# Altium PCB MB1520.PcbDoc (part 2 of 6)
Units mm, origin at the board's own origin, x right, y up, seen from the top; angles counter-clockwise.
Board outline 159 x 88 mm, 6 copper layers (Top Layer, Signal Layer 1, Signal Layer 2, Signal Layer 3, Signal Layer 4, Bottom Layer), stack 1.572 mm thick; 473 components, 377 nets, 1832 pads, 1378 vias.
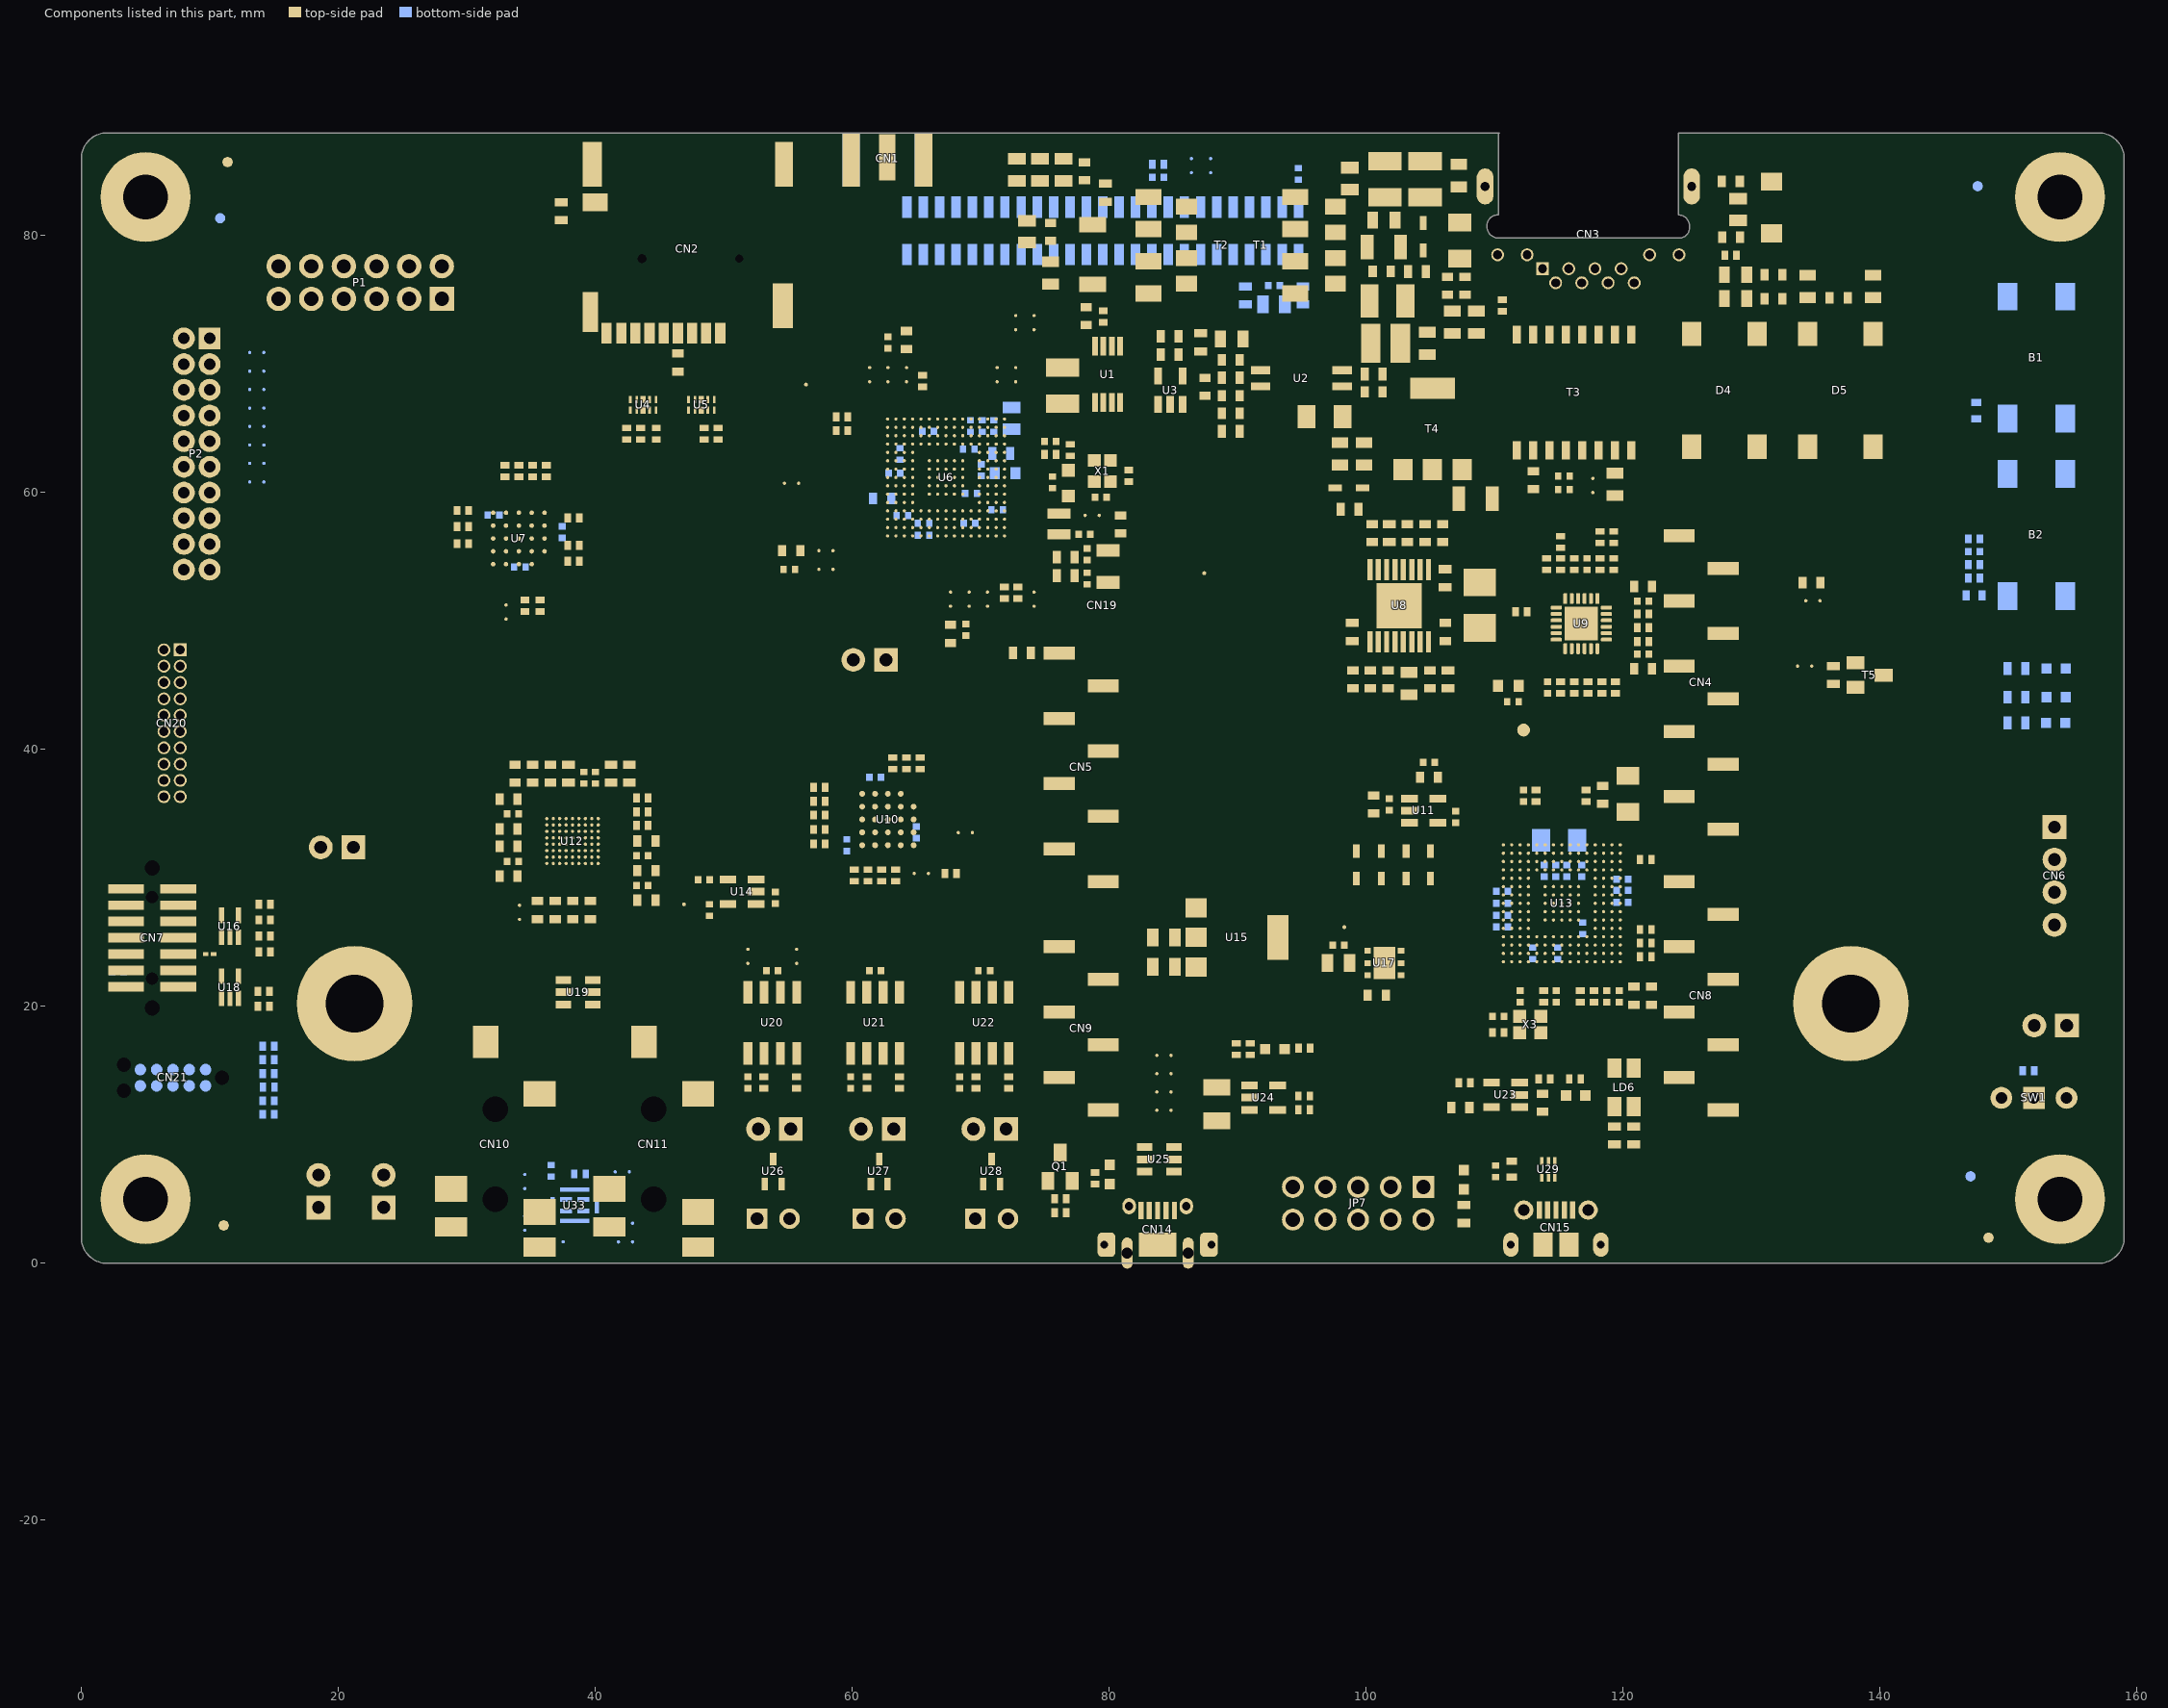
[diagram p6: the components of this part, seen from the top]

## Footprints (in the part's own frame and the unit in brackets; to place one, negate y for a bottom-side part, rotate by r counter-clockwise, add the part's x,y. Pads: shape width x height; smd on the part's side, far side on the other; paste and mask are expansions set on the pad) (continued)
CON_SAMTEC_SQT-110-01-F-D-RA__STMOD+ [mm] "SQT-110-01-F-D-RA (connecteur SAMTEC pour interface STMod+ femelle coté Host) Pinning adapté non conforme SAMTEC."
  rect 1.7x1.7 hole 0.9 mask+0.05: 1(9,1)
  round 1.7 hole 0.9 mask+0.05: 2(7,1) 3(5,1) 4(3,1) 5(1,1) 6(-1,1) 7(-3,1) 8(-5,1) 9(-7,1) 10(-9,1) 11(9,-1) 12(7,-1) 13(5,-1) 14(3,-1) 15(1,-1) 16(-1,-1) 17(-3,-1) 18(-5,-1) 19(-7,-1) 20(-9,-1)
  silkscreen extent -10.15,-8.62 10.15,0.07, body extent -10.15,-8.65 10.15,1.22, height 4
CON_SAMTEC_SSW-106-02-F-D-RA__PMOD [mm] "SSW-106-02-F-D-RA (connecteur SAMTEC pour interface PMOD femelle coté Host) Pinning adapté non conforme SAMTEC."
  rect 1.9x1.9 hole 1.1 mask+0.05: 1(6.35,1.27)
  round 1.9 hole 1.1 mask+0.05: 2(3.81,1.27) 3(1.27,1.27) 4(-1.27,1.27) 5(-3.81,1.27) 6(-6.35,1.27) 7(6.35,-1.27) 8(3.81,-1.27) 9(1.27,-1.27) 10(-1.27,-1.27) 11(-3.81,-1.27) 12(-6.35,-1.27)
  silkscreen extent -7.88,-11.3 7.88,0.23, body extent -7.87,-11.31 7.87,1.47, height 5.21
CON_SAMTEC_SSW-106-22-X-S-VS [mil]
  rect 40x95 smd mask+1.97: 1(250,67.5) 2(150,-67.5) 3(50,67.5) 4(-50,-67.5) 5(-150,67.5) 6(-250,-67.5)
  silkscreen extent -310,-48 310,48, body extent -310,-101 310,102, height 385
CON_SAMTEC_SSW-108-22-X-S-VS [mil]
  rect 40x95 smd mask+1.97: 1(350,67.5) 2(250,-67.5) 3(150,67.5) 4(50,-67.5) 5(-50,67.5) 6(-150,-67.5) 7(-250,67.48) 8(-350,-67.48)
  silkscreen extent -410,-48 410,48, body extent -410,-101 410,102, height 385
CON_SAMTEC_SSW-110-22-X-S-VS [mil]
  rect 40x95 smd mask+1.97: 1(450,67.5) 2(350,-67.5) 3(250,67.5) 4(150,-67.5) 5(50,67.5) 6(-50,-67.5) 7(-150,67.48) 8(-250,-67.48) 9(-350,67.48) 10(-450,-67.48)
  silkscreen extent -510,-48 510,48, body extent -510,-101 510,102, height 385
CON_SAMTEC_TSW-102-07-G-S [mm]
  rect 1.85x1.85 / inner round 1.85 / far side rect 1.85x1.85 hole 1 mask+0.05: 1(-1.27,0)
  round 1.85 hole 1 mask+0.05: 2(1.27,0)
  silkscreen extent -2.58,-1.3 2.58,1.3, body extent -2.67,-1.3 2.58,1.3, height 8.38
CON_SAMTEC_TSW-104-07-G-S [mm]
  rect 1.85x1.85 / inner round 1.85 / far side rect 1.85x1.85 hole 1 mask+0.05: 1(-3.81,0)
  round 1.85 hole 1 mask+0.05: 2(-1.27,0) 3(1.27,0) 4(3.81,0)
  silkscreen extent -5.12,-1.3 5.12,1.3, body extent -5.21,-1.37 5.18,1.37, height 8.38
CON_STDC14_Receiver_MEDIUM_WITH_MIPI10_3D [mm] "compatible with FTSH-105-01-L-DV,-K and FTSH-107-01-L-DV,-K,-A,-P,-ES"
  round 0 hole 1.19 unplated mask+0.05: 0(-5.445,0) 0(5.445,0)
  round 0 hole 0.97 unplated mask+0.05: 0(-3.175,0) 0(3.175,0)
  rect 0.74x2.79 smd mask+0.05: 1(-3.81,-2.032) 2(-3.81,2.032) 3(-2.54,-2.032) 4(-2.54,2.032) 5(-1.27,-2.032) 6(-1.27,2.032) 7(0,-2.032) 8(0,2.032) 9(1.27,-2.032) 10(1.27,2.032) 11(2.54,-2.032) 12(2.54,2.032) 13(3.81,-2.032) 14(3.81,2.032)
  silkscreen extent -6.3,-4.38 6.3,3.6, body extent -6.3,-2.92 6.3,2.92, height 6.6
CON_TAG-C_TC2050-IDC-NL [mm]
  round 0.9 smd paste+0 mask+0.05: 1(-2.54,-0.635) 2(-1.27,-0.635) 3(0,-0.635) 4(1.27,-0.635) 5(2.54,-0.635) 6(2.54,0.635) 7(1.27,0.635) 8(0,0.635) 9(-1.27,0.635) 10(-2.54,0.635)
  round 0 hole 1.1 unplated mask+0.05: 11(-3.81,0) 12(3.81,-1.015) 13(3.81,1.015)
  Multi-Layer keep-out circle w0.01: c3.81,-1.015 r0.75
  Multi-Layer keep-out circle w0.01: c3.81,1.015 r0.75
  Multi-Layer keep-out circle w0.01: c-3.81,0 r0.75
  silkscreen extent -6.22,-3.4 6.22,3.33, body extent -6.28,-3.46 6.28,3.39, height 13
CON_USBMICROAB_MOLEX_47590-0001_H3 [mm]
  rect 0.4x1.35 smd mask+0.05: 1(1.3,4.125) 2(0.65,4.125) 3(0,4.125) 4(-0.65,4.125) 5(-1.3,4.125)
  oval 1.05x1.25 hole 0.65 slot 0.85 at 90 deg mask+0.05: 6(-2.225,4.45) 7(2.225,4.45)
  rrect50% 1.375x1.9 hole 0.6 slot 1.3 at 90 deg copper offset 0.188,0 mask+0.05: 8(-4.175,1.45)
  rrect50% 1.375x1.9 hole 0.6 slot 1.3 at 90 deg copper offset -0.188,0 mask+0.05: 9(4.175,1.45)
  rect 2.9x1.9 smd mask+0.05: 10(0,1.45)
  oval 0.85x2.425 hole 0.85 slot 2.425 at 90 deg unplated mask+0.1: 11(-2.375,0.8) 12(2.375,0.8)
  silkscreen extent -4.1,-1.3 4.1,4.3, body extent -4.32,-1.36 4.33,4.6, height 3
CON_USBMICROB_MOLEX_105017-0001_H2P90 [mm]
  rect 0.4x1.35 smd mask+0.05: 1(-1.3,4.15) 2(-0.65,4.15) 3(0,4.15) 4(0.65,4.15) 5(1.3,4.15)
  round 1.5 hole 0.9 mask+0.05: 6(-2.5,4.15) 7(2.5,4.15)
  oval 1.2x1.9 hole 0.6 slot 1.3 at 90 deg mask+0.05: 8(3.5,1.45) 9(-3.5,1.45)
  rect 1.5x1.9 smd mask+0.05: 10(-1,1.45) 11(1,1.45)
  Top Layer region: -3.5,2.4 -2.3,2.4 -2.3,0.5 -3.5,0.5 -3.5,2.4
  Top Layer region: 2.3,2.4 3.5,2.4 3.5,0.5 2.3,0.5 2.3,2.4
  silkscreen extent -4,-0.7 4,4.6, body extent -4.1,-1.15 4.1,4.66, height 2.9
CPOL_VISHAY_TANTAL-595D_1407_H220 [mm]
  rect 1.3x2.1 smd mask+0.05: 1(-1.3,0) 2(1.3,0)
  silkscreen extent -2.23,-1.32 0.53,1.32, body extent -1.85,-1.05 1.85,1.05, height 2.21
CRY_NX3215SA_2P [mm]
  rect 1x1.8 smd mask+0.05: 1(-1.25,0) 2(1.25,0)
  silkscreen extent -0.63,-0.8 0.63,0.8, body extent -1.65,-0.8 1.65,0.8, height 0.9
DIO_SMA_1A_2K [mm]
  rect 1.4x1.64 smd mask+0.05: 1(2.015,0) 2(-2.015,0)
  silkscreen extent -2.3,-1.45 2.3,1.45, body extent -2.75,-1.45 2.75,1.45, height 2.7
DIO_SMA_DO214-AC_1A_2K [mm]
  rect 2.15x2.5 smd mask+0.05: 1(1.775,0) 2(-1.775,0)
  silkscreen extent -2.25,-1.4 2.25,1.4, body extent -2.75,-1.4 2.75,1.4, height 2.6
DIO_SMB-FLAT_1A_2K [mm]
  rect 1.2x2.07 smd mask+0.05: 1(2.32,0) 2(-2.32,0)
  silkscreen extent -2.3,-2 2.3,2, body extent -2.8,-2 2.8,2, height 1.11
DIO_SOD323 [mm]
  rect 1.06x0.54 smd mask+0.05: 1(-1.07,0) 2(1.07,0)
  silkscreen extent -0.9,-0.72 0.9,0.72, body extent -1.3,-0.78 1.3,0.78, height 1.17
DIO_SOD323_1A_2K [mm]
  rect 1.06x0.54 smd mask+0.05: 1(-1.07,0) 2(1.07,0)
  silkscreen extent -0.9,-0.72 0.9,0.72, body extent -1.3,-0.78 1.3,0.78, height 1.17
DIO_SOT323 [mm]
  rect 0.5x0.95 smd mask+0.05: 1(-0.65,-0.975) 2(0.65,-0.975) 3(0,0.975)
  silkscreen extent -1.15,-0.67 1.15,0.67, body extent -1.15,-1.12 1.15,1.12, height 1.1
ESD_QFN2_1P6X1_P125 [mm]
  rect 0.55x0.8 smd mask+0.05: 1(-0.625,0) 2(0.625,0)
  silkscreen extent -1,-0.55 0.85,0.55, body extent -0.85,-0.55 0.85,0.55, height 0.61
ESD_QFN-6L_1P7X1P5_P050 [mm]
  rect 0.25x0.6 smd mask+0.05: 1(-0.5,-0.65) 2(0,-0.65) 3(0.5,-0.65) 4(0.5,0.65) 5(0,0.65) 6(-0.5,0.65)
  silkscreen extent -0.9,-0.8 0.9,0.8, body extent -0.9,-0.8 0.9,0.8, height 0.56
ESD_SOT23-6L [mm]
  rect 0.6x1.2 smd mask+0.05: 1(-0.95,-1.15) 2(0,-1.15) 3(0.95,-1.15) 4(0.95,1.15) 5(0,1.15) 6(-0.95,1.15)
  silkscreen extent -1.53,-0.87 1.53,0.87, body extent -1.52,-1.5 1.52,1.5, height 1.45
ESD_SOT323-5L [mm]
  rect 0.4x1.2 smd mask+0.05: 1(-0.65,-0.85) 2(0,-0.85) 3(0.65,-0.85) 4(0.65,0.85) 5(-0.65,0.85)
  silkscreen extent -1.22,-1.21 1.22,0.77, body extent -1.15,-1.05 1.15,1.05, height 1.1
ESD_ST0201 [mm]
  rect 0.425x0.33 smd mask+0.05: 1(-0.312,0) 2(0.312,0)
  silkscreen extent -0.55,-0.3 0.33,0.3, body extent -0.34,-0.18 0.34,0.18, height 0.34
ESD_UQFN-10L_2P5X1_P050 [mm]
  rect 0.2x0.58 smd mask+0.05: 1(-1,-0.41) 2(-0.5,-0.41) 4(0.5,-0.41) 5(1,-0.41) 6(1,0.41) 7(0.5,0.41) 9(-0.5,0.41) 10(-1,0.41)
  rect 0.4x0.58 smd mask+0.05: 3(0,-0.41) 8(0,0.41)
  silkscreen extent -1.38,-0.63 1.38,0.63, body extent -1.3,-0.55 1.3,0.55, height 0.51
ICC_BGA24_5X5-BALL-ARRAY_6X8_P1 [mm]
  round 0.45 smd mask+0.05: A2(-1,2) A3(0,2) A4(1,2) A5(2,2) B1(-2,1) B2(-1,1) B3(0,1) B4(1,1) B5(2,1) C1(-2,0) C2(-1,0) C3(0,0) C4(1,0) C5(2,0) D1(-2,-1) D2(-1,-1) D3(0,-1) D4(1,-1) D5(2,-1) E1(-2,-2) E2(-1,-2) E3(0,-2) E4(1,-2) E5(2,-2)
  silkscreen extent -3.05,-4.05 3.05,4.05, body extent -3.05,-4.05 3.05,4.05, height 1.2
ICC_DFN6-EPAD_3X3_P095 [mm]
  rect 0.45x0.5 smd mask+0.05: 1(-0.95,-1.3) 2(0,-1.3) 3(0.95,-1.3) 4(0.95,1.3) 5(0,1.3) 6(-0.95,1.3)
  rect 2.5x1.7 smd mask+0.05: EP(0,0)
  silkscreen extent -1.55,-1.55 1.55,1.55, body extent -1.55,-1.55 1.55,1.55, height 1
ICC_FBGA24_5X5-BALL-ARRAY_6X8_P1 [mm] "MCD-01824"
  round 0.35 smd mask+0.05: A2(-1,2) A3(0,2) A4(1,2) A5(2,2) B1(-2,1) B2(-1,1) B3(0,1) B4(1,1) B5(2,1) C1(-2,0) C2(-1,0) C3(0,0) C4(1,0) C5(2,0) D1(-2,-1) D2(-1,-1) D3(0,-1) D4(1,-1) D5(2,-1) E1(-2,-2) E2(-1,-2) E3(0,-2) E4(1,-2) E5(2,-2)
  silkscreen extent -3.18,-4.05 3.05,4.18, body extent -3.05,-4.05 3.05,4.05, height 1
ICC_HTSSOP16-EPAD_5X4P4_P065 [mm]
  rect 0.4x1.65 smd mask+0.05: 1(-2.275,-2.8) 2(-1.625,-2.8) 3(-0.975,-2.8) 4(-0.325,-2.8) 5(0.325,-2.8) 6(0.975,-2.8) 7(1.625,-2.8) 8(2.275,-2.8) 9(2.275,2.8) 10(1.625,2.8) 11(0.975,2.8) 12(0.325,2.8) 13(-0.325,2.8) 14(-0.975,2.8) 15(-1.625,2.8) 16(-2.275,2.8)
  rect 3.5x3.5 smd mask+0.05: EP(0,0)
  silkscreen extent -2.6,-2.25 2.6,2.25, body extent -2.56,-3.2 2.55,3.2, height 1.2
ICC_SO8_5X4_P127 [mm]
  rect 0.7x1.75 smd mask+0.05: 1(-1.905,-2.375) 2(-0.635,-2.375) 3(0.635,-2.375) 4(1.905,-2.375) 5(1.905,2.375) 6(0.635,2.375) 7(-0.635,2.375) 8(-1.905,2.375)
  silkscreen extent -2.73,-3.25 2.58,2, body extent -2.57,-3 2.57,3, height 1.75
ICC_UFBGA201_176+25_10X10_P065 [mm] "IPC"
  round 0.25 smd mask+0.05: A1(-4.55,4.55) A2(-3.9,4.55) A3(-3.25,4.55) A4(-2.6,4.55) A5(-1.95,4.55) A6(-1.3,4.55) A7(-0.65,4.55) A8(0,4.55) A9(0.65,4.55) A10(1.3,4.55) A11(1.95,4.55) A12(2.6,4.55) A13(3.25,4.55) A14(3.9,4.55) A15(4.55,4.55) B1(-4.55,3.9) B2(-3.9,3.9) B3(-3.25,3.9) B4(-2.6,3.9) B5(-1.95,3.9) B6(-1.3,3.9) B7(-0.65,3.9) B8(0,3.9) B9(0.65,3.9) B10(1.3,3.9) B11(1.95,3.9) B12(2.6,3.9) B13(3.25,3.9) B14(3.9,3.9) B15(4.55,3.9) C1(-4.55,3.25) C2(-3.9,3.25) C3(-3.25,3.25) C4(-2.6,3.25) C5(-1.95,3.25) C6(-1.3,3.25) C7(-0.65,3.25) C8(0,3.25) C9(0.65,3.25) C10(1.3,3.25) C11(1.95,3.25) C12(2.6,3.25) C13(3.25,3.25) C14(3.9,3.25) C15(4.55,3.25) D1(-4.55,2.6) D2(-3.9,2.6) D3(-3.25,2.6) D4(-2.6,2.6) D5(-1.95,2.6) D6(-1.3,2.6) D7(-0.65,2.6) D8(0,2.6) D9(0.65,2.6) D10(1.3,2.6) D11(1.95,2.6) D12(2.6,2.6) D13(3.25,2.6) D14(3.9,2.6) D15(4.55,2.6) E1(-4.55,1.95) E2(-3.9,1.95) E3(-3.25,1.95) E4(-2.6,1.95) E12(2.6,1.95) E13(3.25,1.95) E14(3.9,1.95) E15(4.55,1.95) F1(-4.55,1.3) F2(-3.9,1.3) F3(-3.25,1.3) F4(-2.6,1.3) F6(-1.3,1.3) F7(-0.65,1.3) F8(0,1.3) F9(0.65,1.3) F10(1.3,1.3) F12(2.6,1.3) F13(3.25,1.3) F14(3.9,1.3) F15(4.55,1.3) G1(-4.55,0.65) G2(-3.9,0.65) G3(-3.25,0.65) G4(-2.6,0.65) G6(-1.3,0.65) G7(-0.65,0.65) G8(0,0.65) G9(0.65,0.65) G10(1.3,0.65) G12(2.6,0.65) G13(3.25,0.65) G14(3.9,0.65) G15(4.55,0.65) H1(-4.55,0) H2(-3.9,0) H3(-3.25,0) H4(-2.6,0) H6(-1.3,0) H7(-0.65,0) H8(0,0) H9(0.65,0) H10(1.3,0) H12(2.6,0) H13(3.25,0) H14(3.9,0) H15(4.55,0) J1(-4.55,-0.65) J2(-3.9,-0.65) J3(-3.25,-0.65) J4(-2.6,-0.65) J6(-1.3,-0.65) J7(-0.65,-0.65) J8(0,-0.65) J9(0.65,-0.65) J10(1.3,-0.65) J12(2.6,-0.65) J13(3.25,-0.65) J14(3.9,-0.65) J15(4.55,-0.65) K1(-4.55,-1.3) K2(-3.9,-1.3) K3(-3.25,-1.3) K4(-2.6,-1.3) K6(-1.3,-1.3) K7(-0.65,-1.3) K8(0,-1.3) K9(0.65,-1.3) K10(1.3,-1.3) K12(2.6,-1.3) K13(3.25,-1.3) K14(3.9,-1.3) K15(4.55,-1.3) L1(-4.55,-1.95) L2(-3.9,-1.95) L3(-3.25,-1.95) L4(-2.6,-1.95) L12(2.6,-1.95) L13(3.25,-1.95) L14(3.9,-1.95) L15(4.55,-1.95) M1(-4.55,-2.6) M2(-3.9,-2.6) M3(-3.25,-2.6) M4(-2.6,-2.6) M5(-1.95,-2.6) M6(-1.3,-2.6) M7(-0.65,-2.6) M8(0,-2.6) M9(0.65,-2.6) M10(1.3,-2.6) M11(1.95,-2.6) M12(2.6,-2.6) M13(3.25,-2.6) M14(3.9,-2.6) M15(4.55,-2.6) N1(-4.55,-3.25) N2(-3.9,-3.25) N3(-3.25,-3.25) N4(-2.6,-3.25) N5(-1.95,-3.25) N6(-1.3,-3.25) N7(-0.65,-3.25) N8(0,-3.25) N9(0.65,-3.25) N10(1.3,-3.25) N11(1.95,-3.25) N12(2.6,-3.25) N13(3.25,-3.25) N14(3.9,-3.25) N15(4.55,-3.25) P1(-4.55,-3.9) P2(-3.9,-3.9) P3(-3.25,-3.9) P4(-2.6,-3.9) P5(-1.95,-3.9) P6(-1.3,-3.9) P7(-0.65,-3.9) P8(0,-3.9) P9(0.65,-3.9) P10(1.3,-3.9) P11(1.95,-3.9) P12(2.6,-3.9) P13(3.25,-3.9) P14(3.9,-3.9) P15(4.55,-3.9) R1(-4.55,-4.55) R2(-3.9,-4.55) R3(-3.25,-4.55) R4(-2.6,-4.55) R5(-1.95,-4.55) R6(-1.3,-4.55) R7(-0.65,-4.55) R8(0,-4.55) R9(0.65,-4.55) R10(1.3,-4.55) R11(1.95,-4.55) R12(2.6,-4.55) R13(3.25,-4.55) R14(3.9,-4.55) R15(4.55,-4.55)
  silkscreen extent -5.22,-5.07 5.07,5.23, body extent -5.07,-5.07 5.07,5.07, height 0.61
ICC_VQFN24-EPAD_4X4_P050 [mm]
  rrect50% 0.85x0.3 smd mask+0.05: 1(-1.95,1.25) 2(-1.95,0.75) 3(-1.95,0.25) 4(-1.95,-0.25) 5(-1.95,-0.75) 6(-1.95,-1.25) 13(1.95,-1.25) 14(1.95,-0.75) 15(1.95,-0.25) 16(1.95,0.25) 17(1.95,0.75) 18(1.95,1.25)
  rrect50% 0.3x0.85 smd mask+0.05: 7(-1.25,-1.95) 8(-0.75,-1.95) 9(-0.25,-1.95) 10(0.25,-1.95) 11(0.75,-1.95) 12(1.25,-1.95) 19(1.25,1.95) 20(0.75,1.95) 21(0.25,1.95) 22(-0.25,1.95) 23(-0.75,1.95) 24(-1.25,1.95)
  rect 2.6x2.6 smd paste-10 mask+0.05: EP(0,0)
  silkscreen extent -2,-2 2,2, body extent -2.05,-2.05 2.05,2.05, height 1.1
ICC_VSSOP8_DGK_S-PDSO-G8_3X3_P065 [mm]
  rect 0.45x1.45 smd mask+0.05: 1(-0.975,-2.2) 2(-0.325,-2.2) 3(0.325,-2.2) 4(0.975,-2.2) 5(0.975,2.2) 6(0.325,2.2) 7(-0.325,2.2) 8(-0.975,2.2)
  silkscreen extent -1.55,-1.55 1.55,1.55, body extent -1.55,-2.45 1.55,2.45, height 1.11
ICC_W-CSP-BGA72_4P511X4P023_P050 [mm]
  round 0.25 smd mask+0.05: A1(-2,1.75) A2(-1.5,1.75) A3(-1,1.75) A4(-0.5,1.75) A5(0,1.75) A6(0.5,1.75) A7(1,1.75) A8(1.5,1.75) A9(2,1.75) B1(-2,1.25) B2(-1.5,1.25) B3(-1,1.25) B4(-0.5,1.25) B5(0,1.25) B6(0.5,1.25) B7(1,1.25) B8(1.5,1.25) B9(2,1.25) C1(-2,0.75) C2(-1.5,0.75) C3(-1,0.75) C4(-0.5,0.75) C5(0,0.75) C6(0.5,0.75) C7(1,0.75) C8(1.5,0.75) C9(2,0.75) D1(-2,0.25) D2(-1.5,0.25) D3(-1,0.25) D4(-0.5,0.25) D5(0,0.25) D6(0.5,0.25) D7(1,0.25) D8(1.5,0.25) D9(2,0.25) E1(-2,-0.25) E2(-1.5,-0.25) E3(-1,-0.25) E4(-0.5,-0.25) E5(0,-0.25) E6(0.5,-0.25) E7(1,-0.25) E8(1.5,-0.25) E9(2,-0.25) F1(-2,-0.75) F2(-1.5,-0.75) F3(-1,-0.75) F4(-0.5,-0.75) F5(0,-0.75) F6(0.5,-0.75) F7(1,-0.75) F8(1.5,-0.75) F9(2,-0.75) G1(-2,-1.25) G2(-1.5,-1.25) G3(-1,-1.25) G4(-0.5,-1.25) G5(0,-1.25) G6(0.5,-1.25) G7(1,-1.25) G8(1.5,-1.25) G9(2,-1.25) H1(-2,-1.75) H2(-1.5,-1.75) H3(-1,-1.75) H4(-0.5,-1.75) H5(0,-1.75) H6(0.5,-1.75) H7(1,-1.75) H8(1.5,-1.75) H9(2,-1.75)
  silkscreen extent -2.42,-2.03 2.28,2.17, body extent -2.28,-2.04 2.28,2.04, height 0.78
IND_2016_MURATA_LQM2MPN2R2NG0 [mm]
  rect 0.8x1.8 smd mask+0.05: 1(-0.8,0) 2(0.8,0)
  silkscreen extent -0.28,-0.87 0.28,0.87, body extent -1.07,-0.87 1.08,0.87, height 1
IND_POWER_COILCRAFT_ME3220 [mm]
  rect 1.52x3.05 smd mask+0.05: 1(-1.145,0) 2(1.145,0)
  silkscreen extent -0.25,-1.4 0.25,1.4, body extent -1.75,-1.4 1.75,1.4, height 2.4
IND_TAIYO-YUDEN_FBMJ1608 [mm]
  rect 1x1 smd mask+0.05: 1(-1,0) 2(1,0)
  silkscreen extent -0.38,-0.5 0.38,0.5, body extent -0.9,-0.5 0.9,0.5, height 1
L0603 [mm]
  rect 0.8x0.95 smd mask+0.05: 1(-0.8,0) 2(0.8,0)
  silkscreen extent -1.33,-0.6 1.33,0.6, body extent -0.87,-0.47 0.87,0.47, height 0.95
LED_0603_GREEN [mm]
  rect 0.8x0.8 smd mask+0.05: 1(-0.75,0) 2(0.75,0)
  silkscreen extent -0.25,-0.4 1.25,0.4, body extent -0.8,-0.4 0.8,0.4, height 0.6
LED_0603_RED [mm]
  rect 0.8x0.8 smd mask+0.05: 1(-0.75,0) 2(0.75,0)
  silkscreen extent -0.25,-0.4 1.25,0.4, body extent -0.8,-0.4 0.8,0.4, height 0.6
LED_0603_VISHAY_VLMS1300-GS08_RED_1A2K_H0P8 [mm]
  rect 0.8x0.8 smd mask+0.05: 1(-0.75,0) 2(0.75,0)
  silkscreen extent -0.85,-0.53 1.28,0.53, body extent -0.85,-0.45 0.85,0.45, height 0.8
LED_0603_VISHAY_VLMTG1300-GS08_GREEN_1A2K_H0P8 [mm]
  rect 0.8x0.8 smd mask+0.05: 1(-0.75,0) 2(0.75,0)
  silkscreen extent -0.85,-0.53 1.28,0.53, body extent -0.85,-0.45 0.85,0.45, height 0.8
LED_BI-GR_HSMF-A201-A00J1 [mm]
  rect 1.1x1.5 smd mask+0.05: 1(-0.75,-1.5) 2(-0.75,1.5) 3(0.75,1.5) 4(0.75,-1.5)
  silkscreen extent -1.65,-1.85 1.65,1.85, body extent -1.5,-1.85 1.5,1.85, height 2.1
LOGO_ETIQUETTE [mm]
  silkscreen extent 0,0 27,10
MIC_HCLGA_3X4X1_4LD [mm]
  rect 0.4x0.95 smd paste+0 mask+0.05: 1(0.45,-0.675) 2(0.45,0.675) 3(-0.45,0.675) 4(-0.45,-0.675)
  rect 1.3x0.35 smd paste+0 mask+0.05: 5(0,-1.725) 6(0,1.725)
  rect 0.35x2.3 smd paste+0 mask+0.05: 7(1.225,0) 8(-1.225,0)
  silkscreen extent -1.55,-2.05 1.55,2.05, body extent -1.45,-1.95 1.45,1.95, height 1.03
MIRE_PLACE_SMD_0P8MM [mm]
  round 0.8 smd paste-10 mask+0.2: 1(0,0)
  Top Layer keep-out circle w0.01: c0,0 r0.804
MOD_LCD_MB1046B__CON_SAMTEC_FLE-125-01-G-DV [mm]
  rect 0.74x1.675 smd mask+0.05: 1(15.24,-9.469) 2(15.24,-5.783) 3(13.97,-9.469) 4(13.97,-5.783) 5(12.7,-9.469) 6(12.7,-5.783) 7(11.43,-9.469) 8(11.43,-5.783) 9(10.16,-9.469) 10(10.16,-5.783) 11(8.89,-9.469) 12(8.89,-5.783) 13(7.62,-9.469) 14(7.62,-5.783) 15(6.35,-9.469) 16(6.35,-5.783) 17(5.08,-9.469) 18(5.08,-5.783) 19(3.81,-9.469) 20(3.81,-5.783) 21(2.54,-9.469) 22(2.54,-5.783) 23(1.27,-9.469) 24(1.27,-5.783) 25(0,-9.469) 26(0,-5.783) 27(-1.27,-9.469) 28(-1.27,-5.783) 29(-2.54,-9.469) 30(-2.54,-5.783) 31(-3.81,-9.469) 32(-3.81,-5.783) 33(-5.08,-9.469) 34(-5.08,-5.783) 35(-6.35,-9.469) 36(-6.35,-5.783) 37(-7.62,-9.469) 38(-7.62,-5.783) 39(-8.89,-9.469) 40(-8.89,-5.783) 41(-10.16,-9.469) 42(-10.16,-5.783) 43(-11.43,-9.469) 44(-11.43,-5.783) 45(-12.7,-9.469) 46(-12.7,-5.783) 47(-13.97,-9.469) 48(-13.97,-5.783) 49(-15.24,-9.469) 50(-15.24,-5.783)
  round 9 hole 4.5 mask+0.05: PTH1(-58.24,-67.77) PTH2(58.24,-67.77)
  silkscreen extent -63.5,-73 63.5,0, body extent -63.5,-73 63.5,0, height 10.2
MOS_SOT23 [mm]
  rect 1x1.4 smd mask+0.05: 1(-0.95,-1.1) 2(0.95,-1.1) 3(0,1.1)
  silkscreen extent -1.63,-0.82 1.63,0.82, body extent -1.56,-1.25 1.56,1.25, height 1.1
MOS_SOT23-5L [mm]
  rect 0.6x1.3 smd mask+0.05: 1(-0.95,-1.1) 2(0,-1.1) 3(0.95,-1.1) 4(0.95,1.1) 5(-0.95,1.1)
  silkscreen extent -1.6,-0.95 1.6,0.97, body extent -1.52,-1.25 1.52,1.25, height 1.45
MOS_SOT223-TAB [mm]
  rect 1.5x1.65 smd mask+0.05: 1(-2.3,-3.175) 2(0,-3.175) 3(2.3,-3.175)
  rect 3.5x1.65 smd mask+0.05: 4(0,3.175)
  silkscreen extent -3.35,-2.15 3.35,2.12, body extent -3.35,-3.48 3.35,3.48, height 1.8
NPN_SOT23 [mm]
  rect 1x1.4 smd mask+0.05: 1(-0.95,-1.1) 2(0.95,-1.1) 3(0,1.1)
  silkscreen extent -1.63,-0.82 1.63,0.82, body extent -1.56,-1.25 1.56,1.25, height 1.1
OPT_MINI-FLAT_FAIRCHILD_HMHA2801A [mm]
  rect 0.61x1.52 smd mask+0.05: 1(0.635,3.175) 2(-0.635,3.175) 3(-0.635,-3.175) 4(0.635,-3.175)
  silkscreen extent -1.35,-2.2 1.35,2.2, body extent -1.35,-3.5 1.35,3.5, height 2.39
OSC_NDK_NZ2520SB_4P [mm]
  rect 1x1 smd mask+0.05: 1(-0.825,-0.625) 2(0.825,-0.625) 3(0.825,0.625) 4(-0.825,0.625)
  silkscreen extent -1.43,-1.22 1.2,1.05, body extent -1.3,-1.05 1.3,1.05, height 0.91
PTH_350_700 [mm]
  round 7 hole 3.5 mask+0.05: 1(0,0)
  silkscreen extent -3.75,-3.75 3.75,3.75
R0402 [mm]
  rect 0.51x0.7 smd mask+0.05: 1(-0.45,0) 2(0.45,0)
  silkscreen extent 0,-0.3 0,0.3, body extent -0.52,-0.3 0.52,0.3, height 0.4
R0603 [mm]
  rect 0.64x1 smd mask+0.05: 1(-0.7,0) 2(0.7,0)
  silkscreen extent -1.05,-0.58 1.05,0.58, body extent -0.9,-0.5 0.9,0.5, height 0.56
R0805 [mm]
  rect 0.85x1.3 smd mask+0.05: 1(-0.875,0) 2(0.875,0)
  silkscreen extent -0.33,-0.67 0.33,0.67, body extent -1.05,-0.68 1.05,0.68, height 0.65
R1206_H0P55 [mm]
  rect 1x1.9 smd mask+0.05: 1(-1.3,0) 2(1.3,0)
  silkscreen extent -0.67,-0.85 0.67,0.85, body extent -1.6,-0.85 1.6,0.85, height 0.65
REG_SOT23-5L [mm]
  rect 0.6x1.3 smd mask+0.05: 1(-0.95,-1.1) 2(0,-1.1) 3(0.95,-1.1) 4(0.95,1.1) 5(-0.95,1.1)
  silkscreen extent -1.6,-0.95 1.6,0.97, body extent -1.52,-1.25 1.52,1.25, height 1.1
REG_SOT223-TAB [mm]
  rect 1.5x1.65 smd mask+0.05: 1(-2.3,-3.175) 2(0,-3.175) 3(2.3,-3.175)
  rect 3.5x1.65 smd mask+0.05: 4(0,3.175)
  silkscreen extent -3.35,-2.15 3.35,2.12, body extent -3.35,-3.48 3.35,3.48, height 1.8
SOLDER-BRIDGE_R0603-0R [mil]
  round 10 smd paste-393.7: 1(-19.69,0) 2(23.62,0)
  Top Layer region: -5.91,19.68 13.78,0 -5.91,-19.68 47.24,-19.68 47.24,19.68 -5.91,19.68
  Top Layer region: -47.24,-19.68 -47.24,19.68 -15.75,19.68 3.94,0 -15.75,-19.68 -47.24,-19.68
  silkscreen extent -50,-23 50,23, body extent -36,-20 36,20, height 22
SWI_EAO_09-03290-01_EXTENDED_STRAIGHT_BLACK [mm]
  rect 1.7x1.7 hole 0.9 mask+0.05: 1(0,0)
  round 1.7 hole 0.9 mask+0.05: 2(0,-2.54) 3(0,2.54)
  silkscreen extent -1.25,-5 1.25,5, body extent -1.25,-5 1.25,5, height 7.9
SWI_WEALTHMETAL_TD-0341_4P_BLACK [mm]
  rect 1.52x2.16 smd mask+0.05: 1(-2.25,-4.75) 2(-2.25,4.75) 3(2.25,-4.75) 4(2.25,4.75)
  silkscreen extent -3,-3.5 3,3.5, body extent -3,-5.15 3,5.15, height 7.55
SWI_WEALTHMETAL_TD-0341_4P_BLUE [mm]
  rect 1.52x2.16 smd mask+0.05: 1(-2.25,-4.75) 2(-2.25,4.75) 3(2.25,-4.75) 4(2.25,4.75)
  silkscreen extent -3,-3.5 3,3.5, body extent -3,-5.15 3,5.15, height 7.55
TP_SMD_0-3MM [mm]
  round 0.3 smd paste-10 mask+0.05: 1(0,0)
  silkscreen extent -0.3,-0.3 0.3,0.3
TP_SMD_1MM [mm]
  round 1 smd paste-10 mask+0.05: 1(0,0)
  silkscreen extent -0.7,-0.7 0.7,0.7
TRS_COILCRAFT_POE30P-50L [mm]
  rect 2.03x1.27 smd mask+0.05: 1(-5.715,-3.75) 2(-5.715,-1.25) 3(-5.715,1.25) 4(-5.715,3.75) 5(5.715,3.75) 6(5.715,1.25) 7(5.715,-1.25) 8(5.715,-3.75)
  silkscreen extent -4.57,-5.48 4.57,5.48, body extent -6.6,-5.46 6.6,5.46, height 9.02
TRS_PULSE_H2019NL [mm]
  rect 0.64x1.4 smd mask+0.05: 1(-4.445,-4.51) 2(-3.175,-4.51) 3(-1.905,-4.51) 4(-0.635,-4.51) 5(0.635,-4.51) 6(1.905,-4.51) 7(3.175,-4.51) 8(4.445,-4.51) 9(4.445,4.51) 10(3.175,4.51) 11(1.905,4.51) 12(0.635,4.51) 13(-0.635,4.51) 14(-1.905,4.51) 15(-3.175,4.51) 16(-4.445,4.51)
  silkscreen extent -6.35,-3.7 6.35,3.7, body extent -6.35,-4.7 6.35,4.7, height 5.98
TRS_WURTH_750315923 [mm]
  rect 1.63x1.22 smd mask+0.05: 1(-5.79,3) 2(-5.79,1) 3(-5.79,-1) 4(-5.79,-3) 5(5.79,-3) 6(5.79,-1) 7(5.79,1) 8(5.79,3)
  silkscreen extent -4.85,-6.02 4.85,6.02, body extent -6.43,-6.02 6.43,6.02, height 6.11

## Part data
B1: library part MCD-00001, "Non-Open Push-Button 0.1A 24V BLACK", Manufacturer=WEALTHMETAL, Manufacturer_Part_Number=TD-0341X-A00, Package=6x6mm
B2: library part MCD-00002, "Non-Open Push-Button 0.1A 24V", Manufacturer=WEALTHMETAL, Manufacturer_Part_Number=TD-0341X-GO0, Package=6x6mm
C1 C2 C18: library part MCD-02212, "Capacitor, MLCC, 4.7uF, 100V, X7S, +/-10%, 1210, T=2mm", Manufacturer=TDK, Manufacturer_Part_Number=CGA6M3X7S2A475K200AB, Package=1210
C3 C4 C5 C11: library part MCD-00204, "Capacitor, MLCC, 47uF, 10V, X5R, 20%, 0805, T=1,25mm", Manufacturer=MURATA, Manufacturer_Part_Number=GRM21BR61A476ME15K, Package=0805
C6 C49: library part MCD-00211, "Capacitor, MLCC, 100nF, 16V, X7R, 10%, 0603, T=0,8mm", Manufacturer=YAGEO, Manufacturer_Part_Number=CC0603KRX7R7BB104, Package=0603
C7 C9: library part MCD-01093, "Capacitor,100nF,100V,X7R,10%,0805", Manufacturer=TDK, Manufacturer_Part_Number=C2012X7R2A104K125AA, Package=0805
C8 C13 C15 C16 C17 C19 C20 C52 C59: library part MCD-01091, "Capacitor,1nF,100V,X7R,10%,0603", Manufacturer=YAGEO, Manufacturer_Part_Number=CC0603KRX7R0BB102, Package=0603
C10 C30: library part MCD-00722, "Capacitor, MLCC, 1nF, 2KV, X7R, 10%, 1206, T=1,25mm", Manufacturer=YAGEO, Manufacturer_Part_Number=CC1206KKX7RDBB102, Package=1206
C12: library part MCD-01095, "Capacitor,560pF,16V,X7R,10%,0603", Manufacturer=AVX, Manufacturer_Part_Number=0603YC561KAT2A, Package=0603
C14: library part MCD-01096, "Capacitor,27pF,100V,NPO,5%,0603", Manufacturer=YAGEO, Manufacturer_Part_Number=CC0603JRNPO0BN270, Package=0603
C21 C50 C70 C78 C79 C83 C89 C90 C102 C113 C114 C130: library part MCD-00010, "Capacitor, MLCC, 1uF, 16V, X5R, 10%, 0603, T=0,8mm", Manufacturer=YAGEO, Manufacturer_Part_Number=CC0603KRX5R7BB105, Package=0603
C22 C44 C53 C64 C65 C66 C71: library part MCD-00012, "Capacitor, MLCC, 2.2uF, 10V, X5R, 10%, 0603, T=0,8mm", Alternate_Manufacturer=KEMET, Alternate_Manufacturer_Part_Number=C0603C225K8PACTU, Manufacturer=YAGEO, Manufacturer_Part_Number=CC0603KRX5R6BB225, Package=0603
C23 C47 C54 C137: library part MCD-01356, "Capacitor, MLCC, 4.7uF, 6V3, X5R, 20%, 0402, T=0,5mm", Manufacturer=MURATA, Manufacturer_Part_Number=GRM155R60J475ME47, Package=0402
C24: library part MCD-01721, "Capacitor, MLCC, 4.7uF, 10V, X5R, +/-10%, 0603, T=0.8mm", Manufacturer=YAGEO, Manufacturer_Part_Number=CC0603KRX5R6BB475, Package=0603
C25 C42: library part MCD-01100, "Capacitor,1uF,25V,X5R,10%,0603", Manufacturer=YAGEO, Manufacturer_Part_Number=CC0603KRX5R8BB105, Package=0603
C26: library part MCD-00614, "Capacitor, MLCC, 22uF, 16V, 1210, X7R, 20%, T=2,5mm, ESR 2mohm@410KHz", Manufacturer=MURATA, Manufacturer_Part_Number=GCM32ER71C226ME19, Package=1210
C27: library part MCD-01101, "Capacitor,100pF,50V,X7R,10%,0603", Manufacturer=AVX, Manufacturer_Part_Number=06035C101JAT4A, Package=0603
C28 C40 C41 C57: library part MCD-01099, "Capacitor,100nF,50V,X7R,10%,0603", Manufacturer=YAGEO, Manufacturer_Part_Number=CC0603KRX7R9BB104, Package=0603
C29 C33: library part MCD-01103, "Capacitor,22nF,50V,X7R,10%,0603", Manufacturer=YAGEO, Manufacturer_Part_Number=CC0603KRX7R9BB223, Package=0603
C31: library part MCD-00017, "Capacitor, MLCC, 10nF, 50V, X7R, +/-10%, 0603, T=0.8mm", Manufacturer=YAGEO, Manufacturer_Part_Number=CC0603KRX7R9BB103, Package=0603
C32 C34 C36 C37 C46 C55 C61 C62 C63 C68 C69 C75 C77 C81 C82 C86 C95 C98 C99 C100 C103 C104 C105 C106 C108 C109 C110 C111 C121 C122 C124 C125 C126 C127 C128 C129 C131 C132 C133 C134 C135 C136 C138 C139 C140 C141 C143 C144 C145 C146 C147 C148 C149 C150 C151 C152 C153 C154 C155 C156 C157 C158: library part MCD-00006, "Capacitor, MLCC, 100nF, 16V, X7R, +/-10%, 0402, T=0.5mm", Manufacturer=YAGEO, Manufacturer_Part_Number=CC0402KRX7R7BB104, Package=0402
C35: library part MCD-01355, "Capacitor, MLCC, 10uF, 4V, X5R, 20%, 0402, T=0,5mm", Manufacturer=MURATA, Manufacturer_Part_Number=GRM155R60G106ME44, Package=0402
C38: library part MCD-01341, "Capacitor, MLCC, 10uF, 6V3, X5R, 20%, 0603, T=0,8mm", Manufacturer=MURATA, Manufacturer_Part_Number=GRM188R60J106ME47D, Package=0603
C39: library part MCD-01104, "Capacitor,470pF,100V,X7R,10%,0603", Manufacturer=AVX, Manufacturer_Part_Number=06031C471KAT2A, Package=0603
C43: library part MCD-01225, "Capacitor, MLCC, 220pF, 50V, NPO, 5%, 0402, T=0,5mm", Manufacturer=YAGEO, Manufacturer_Part_Number=CC0402JRNPO9BN221, Package=0402
C45 C48: library part MCD-00563, "Capacitor, MLCC, 1.5pF, 50V, NPO, +-0.25pF, 0402, T=0,5mm", Manufacturer=YAGEO, Manufacturer_Part_Number=CC0402CRNPO9BN1R5, Package=0402
C51: library part MCD-00724, "Capacitor, MLCC, 470pF, 50V, NPO, 5%, 0402, T=0,5mm", Manufacturer=YAGEO, Manufacturer_Part_Number=CC0402JRNPO9BN471, Package=0402
C56: library part MCD-01124, "Capacitor, MLCC, 10uF, 10V, X5R, 10%, 0603, T=0.8mm", Manufacturer=MURATA, Manufacturer_Part_Number=GRM188R61A106KAAL, Package=0603
C58 C60: library part MCD-01098, "Capacitor,10nF,100V,X7R,10%,0603", Manufacturer=YAGEO, Manufacturer_Part_Number=CC0603KRX7R0BB103, Package=0603
C67 C142: library part MCD-00008, "Capacitor, MLCC, 2.2uF, 16V, X7R, 10%, 1206, T=1,15mm", Alternate_Manufacturer=KEMET, Alternate_Manufacturer_Part_Number=C1206C225K4RAC, Manufacturer=YAGEO, Manufacturer_Part_Number=CC1206KKX7R7BB225, Package=1206
C72: library part MCD-00016, "Capacitor, MLCC, 20pF, 50V, NPO, 5%, 0402, T=0,5mm", Manufacturer=YAGEO, Manufacturer_Part_Number=CC0402JRNPO9BN200, Package=0402
C73: library part MCD-00238, "Capacitor, MLCC, 1uF, 6V3, X5R, 10%, 0603, T=0,8mm", Manufacturer=YAGEO, Manufacturer_Part_Number=CC0603KRX5R5BB105, Package=0603
C74 C80 C84 C88 C91 C92 C101: library part MCD-00009, "Capacitor, MLCC, 4.7uF, 16V, X5R, 10%, 0603, T=0.8mm", Manufacturer=YAGEO, Manufacturer_Part_Number=CC0603KRX5R7BB475, Package=0603
C76 C85: library part MCD-00011, "Capacitor, MLCC, 10nF, 16V, X7R, 10%, 0402, T=0.5mm", Manufacturer=YAGEO, Manufacturer_Part_Number=CC0402KRX7R7BB103, Package=0402
C87 C93: library part MCD-00095, "Capacitor, MLCC, 1uF, 6V3, X5R, 10%, 0402, T=0,5mm", Alternate_Manufacturer=MURATA, Alternate_Manufacturer_Part_Number=GRM155R60J105KE19, Manufacturer_Part_Number=GRM155R61E105KA12, Package=0402
C94 C96 C97 C119 C120: library part MCD-00014, "Capacitor, MLCC, 10uF, 25V, X5R, 10%, 0805, T=0,85mm", Manufacturer=YAGEO, Manufacturer_Part_Number=CC0805KRX5R8BB106, Package=0805
C107: library part MCD-00097, "Capacitor, MLCC, 4.7uF, 16V, X5R, 20%, 0603, T=0,8mm", Alternate_Manufacturer=Murata, Alternate_Manufacturer_Part_Number=GRM188R61C475MAAJ, Manufacturer=MURATA, Manufacturer_Part_Number=GRM188R61C475KE11, Package=0603
C112: library part MCD-00595, "Capacitor, Tantalum, 4.7uF, 16V, +/-10%, 595D case A", Manufacturer=VISHAY, Manufacturer_Part_Number=595D475X9016A2T, Package="3718 (metric)"
C115: library part MCD-00205, "Capacitor, MLCC, 100pF, 50V, NPO, 5%, 0402, T=0,5mm", Manufacturer=YAGEO, Manufacturer_Part_Number=CC0402JRNPO9BN101, Package=0402
C116 C117 C118: library part MCD-00006, "Capacitor, MLCC, 100nF, 16V, X7R, 10%, 0402, T=0.5mm", Manufacturer=YAGEO, Manufacturer_Part_Number=CC0402KRX7R7BB104, Package=0402
C123: library part MCD-01722, "Capacitor, 1uF, 10V, X5R, 10%, 0402, T=0.5mm", Manufacturer=YAGEO, Manufacturer_Part_Number=CC0402KRX5R6BB105, Package=0402
CN1: library part MCD-00279, "RF SMA connector PCB edge", Manufacturer=SAMTEC
CN2: library part MCD-00023, "MicroSD Card Conn, Reversed-Type, Mnt Push-Push, Positionning holes", Manufacturer=YAMAICHI, Manufacturer_Part_Number=PJS008-2003-1
CN3: library part MCD-00717, "RJ45 jack, single port, with LEDS, Metal shielded dip low profile", Manufacturer="DONGGUAN KEYOUDA ELECTRONIC TECHNOLOGY", Manufacturer_Part_Number=KRJ-CB4.2GYZNL
CN4: library part MCD-00301, "Socket, 10x1, 2.54mm, VR, SMT, Height 9.78mm", Manufacturer=SAMTEC, Manufacturer_Part_Number=SSW-110-22-L-S-VS
CN5 CN8: library part MCD-00300, "Socket, 8x1, 2.54mm, VR, SMT, Height 9.78mm", Manufacturer=SAMTEC, Manufacturer_Part_Number=SSW-108-22-L-S-VS
CN6: library part MCD-00029, "Header, 4x1, 2,54mm, VR, TH, Height 5.84mm/2.54mm", Manufacturer=SAMTEC, Manufacturer_Part_Number=TSW-104-07-G-S
CN7: library part MCD-01226, "Header 5x2, 1.27mm, Dual row, Straight, Surface mount, vertical male connector. 3.05mm lead. Mates with FFSD connector. Footprint compatible with FTSH-107-01-L-DV,-K,-A,-P,-ES (STDC14 MEDIUM)", Alternate_Manufacturer=JIUBABA, Alternate_Manufacturer_Part_Number=P127B-2x05MGF-079-1A, Manufacturer=SAMTEC, Manufacturer_Part_Number=FTSH-105-01-L-DV-K
CN9: library part MCD-00299, "Socket, 6x1, 2.54mm, VR, SMT, Height 9.78mm", Manufacturer=SAMTEC, Manufacturer_Part_Number=SSW-106-22-L-S-VS
CN10: library part MCD-00018, "Connector Jack socket Stereo 3.5mm, 3 pins, RA, SMT, Green (Line output)", Alternate_Manufacturer=QIAOD, Alternate_Manufacturer_Part_Number=PJ30280-3_GR, Manufacturer_Part_Number=PJ3028B-3_GR
CN11: library part MCD-00682, "Connector Jack socket Stereo 3.5mm, 3 pins, RA, SMT, Blue (Line input)", Alternate_Manufacturer=QIAOD, Alternate_Manufacturer_Part_Number=PJ30280-3_BE, Manufacturer_Part_Number=PJ3028B-3_BE
CN12 CN13 JP2 JP3 JP4 JP5 JP6: library part MCD-00045, "Header, 2x1, 2,54mm, VR, TH, Height 5.84mm/2.54mm", Alternate_Manufacturer=JIUBABA, Alternate_Manufacturer_Part_Number=313102S111116, Manufacturer=SAMTEC, Manufacturer_Part_Number=TSW-102-07-G-S
CN14: library part MCD-00022, "USB-MICRO-AB, 0.65mm, RA, SMT, Top Mount (compatible with MCD-00661 USB certified)", Alternate_Manufacturer=HIROSE, Alternate_Manufacturer_Part_Number=ZX62RD-AB-5P8(30), Manufacturer=MOLEX, Manufacturer_Part_Number=47590-0001
CN15: library part MCD-00028, "USB-MICRO-B, 0.65mm, RA, SMT, Bottom Mount,", Manufacturer=MOLEX, Manufacturer_Part_Number=1050170001
CN16 CN17 CN18: library part MCD-00314, "Header, 2x1, 2.54mm, VR, TH, Height 6mm/3mm", Manufacturer=JIUBABA, Manufacturer_Part_Number=PHFS25-11-02-G0B115-T-1
CN19: library part MCD-01222, "Header 25x2 for MB1046 - LCD 4.3 inches daughter board", Manufacturer=SAMTEC, Manufacturer_Part_Number=FLE-125-01-G-DV
CN20: library part MCD-00147, "Socket for MB1299, 10x2, 1.27mm, VR, TH, Height 4.30mm/2.40mm", Alternate_Manufacturer=JIUBABA, Alternate_Manufacturer_Part_Number=234220S1410, Manufacturer="AMPHENOL ICC", Manufacturer_Part_Number=20021311-00020T4LF
CN21: library part MCD-00031, "Tag_Connector Header, 10x2, No legs", Manufacturer=N/A
D1: library part MCD-01083, "Transil 400W, VRM=58V", Manufacturer=STMICROELECTRONICS, Manufacturer_HQ_COO=EU, Package=SMA
D2: library part MCD-01087, "Low drop power Schottky rectifier(2A, 40V, 0.34V)", Manufacturer=STMICROELECTRONICS, Manufacturer_HQ_COO=EU, Package=SMBflat
D3 D6: library part MCD-01064, "Schottky Single diode,150mA, 100V", Manufacturer=STMICROELECTRONICS, Manufacturer_HQ_COO=EU, Manufacturer_Part_Number=BAT46JFILM, Package=SOD-323
D4 D5: library part MCD-02211, "Surface Mount Bridge Rectifier 1A 100V", Manufacturer=VISHAY, Manufacturer_Part_Number=DF01S-E3/77, Package=DFS
D7: library part MCD-01165, "High voltage power Schottky rectifier", Manufacturer=STMICROELECTRONICS, Manufacturer_HQ_COO=EU, Manufacturer_Part_Number=STPS1H100A
D8 D9 D10 D11: library part MCD-00034, Manufacturer=STMICROELECTRONICS, Manufacturer_HQ_COO=EU
H1 H2 H3 H4: library part MCD-00328, "POSITION HOLE C7D3R5", Manufacturer=n/a
JP1: library part MCD-00683, "Header, 2x1, 2,54mm, VR, TH, Height 5.84mm/2.54mm - Shunt Fitted by default", Manufacturer=SAMTEC, Manufacturer_Part_Number=TSW-102-07-G-S
JP7: library part MCD-00312, "Header, 5x2, 2.54mm, VR, TH, Height 6mm/3mm", Manufacturer=JIUBABA, Manufacturer_Part_Number=PHFS25-12-10-G0B115-T-1
L1: library part MCD-01109, "Power Inductor, 5.6uH, 0.2R, ME3220-562ML", Manufacturer=COILCRAFT, Manufacturer_Part_Number=ME3220-562ML, Package=1210
L2: library part MCD-03956, "Ferrite bead, 18R @ 100MHz, 750mA, 0R004, 0603, T=1mm", Manufacturer="TAIYO YUDEN", Manufacturer_Part_Number=LSMCA160808T180NGR, Package=0603
L3: library part MCD-01110, "Inductor 2.2uH, 2x1.6x0.9mm", Manufacturer=MURATA, Manufacturer_Part_Number=LQM2MPN2R2NG0, Package=0806
L4 L5: library part MCD-00047, "SMD Chip ferrite bead, 600R@100MHz +/-25%, 350mA, 500mohm DC, 0603, T=0.8mm", Manufacturer=TAI-TECH, Manufacturer_Part_Number=FCM1608KF-601T03, Package=0603
LD1 LD4 LD8: library part MCD-02900, "LED, Green, 2V, 20mA, 0603", Manufacturer=EVERLIGHT, Manufacturer_Part_Number=19-213SYGC/S530-E2/5T, Package=0603
LD2 LD7: library part MCD-02899, "LED, Red, 2V35, 20mA, 0603", Manufacturer=EVERLIGHT, Manufacturer_Part_Number=19-213/R6C-AP1Q2B/5T, Package=0603
LD3: library part MCD-00587, "LED Red, 0603 SMD, 2V Forward Voltage", Alternate_Manufacturer="OSRAM OPTO SEMICONDUCTORS", Alternate_Manufacturer_Part_Number="LS Q976-NR-1", Manufacturer=VISHAY, Manufacturer_Part_Number=VLMS1300-GS08, Package="LED 0603"
LD5: library part MCD-00589, "LED Green, 0603 SMD, Fw Voltage = 2.8V - 3.6V", Alternate_Manufacturer="OSRAM OPTO SEMICONDUCTORS", Alternate_Manufacturer_Part_Number="LG Q396-PS-35", Manufacturer=VISHAY, Manufacturer_Part_Number=VLMTG1300-GS08, Package="LED 0603"
LD6: library part MCD-02402, "LED Bicolor", Manufacturer=EVERLIGHT, Manufacturer_Part_Number=67-22SURSYGC/S530-A2/TR8
P1: library part MCD-00308, "Socket, 6x2, 2.54mm, TH, RA, Height 8.51mm/7.62mm", Manufacturer=SAMTEC, Manufacturer_Part_Number=SSW-106-02-F-D-RA
P2: library part MCD-00309, "Socket 10x2, 2.00mm, RA, TH, Height 6.35mm/2.29mm", Alternate_Manufacturer=JIUBABA, Alternate_Manufacturer_Part_Number=FH200020C-12300, Manufacturer=SAMTEC, Manufacturer_Part_Number=SQT-110-01-F-D-RA
Q1: library part MCD-00073, "NPN Bipolar Transistor", Alternate_Manufacturer="ON SEMICONDUCTOR", Alternate_Manufacturer_Part_Number="MMBT2222ALT1G / MMBT2222ALT3G", Manufacturer_Part_Number=BSR14, Package=SOT23
R1 R10 R11 R18 R33 R42: library part MCD-00179, "Resistor,0R,0805,5%", Manufacturer=YAGEO, Manufacturer_Part_Number=RC0805JR-070RL, Package=0805
R2 R61 R137 R138 R139: library part MCD-00056, "Resistor,0R,0603,5%,1/10W", Manufacturer=YAGEO, Manufacturer_Part_Number=RC0603JR-070RL, Package=0603
R3 R8 R23 R44: library part MCD-00220, "Resistor,10K,0603,1%,1/10W", Manufacturer=YAGEO, Manufacturer_Part_Number=RC0603FR-0710KL, Package=0603
R4: library part MCD-01115, "Resistor,68R,0805,1%", Manufacturer=YAGEO, Manufacturer_Part_Number=RC0805FR-0768RL, Package=0805
R5: library part MCD-01114, "Resistor,200R,1206,1%", Manufacturer="ROHM SEMICONDUCTOR", Manufacturer_Part_Number=LTR18EZPF2000, Package=1206
R6 R13 R132 R141: library part MCD-00062, "Resistor,330R,0402,1%,1/16W", Manufacturer=YAGEO, Manufacturer_Part_Number=RC0402FR-07330RL, Package=0402
R7: library part MCD-01113, "Resistor,15R,0805,1%", Manufacturer=YAGEO, Manufacturer_Part_Number=RC0805FR-0715RL, Package=0805
R9 R12 R14 R15: library part MCD-01112, "Resistor,75R,0805,1%", Manufacturer=YAGEO, Manufacturer_Part_Number=RC0805FR-0775RL, Package=0805
R16: library part MCD-00166, "Resistor,120K,0402,1%,1/16W", Manufacturer=YAGEO, Manufacturer_Part_Number=RC0402FR-07120KL, Package=0402
R17: library part MCD-01111, "Resistor,10R,0805,1%,Stackpole,1/4W", Manufacturer=STACKPOLE, Manufacturer_Part_Number=RNCP0805FTD10R0, Package=0805
R19 R21: library part MCD-00384, "Resistor,13K,0603,1%,1/10W", Manufacturer=YAGEO, Manufacturer_Part_Number=RC0603FR-0713KL, Package=0603
R20: library part MCD-00422, "Resistor,20K,0603,1%,1/10W", Manufacturer=YAGEO, Manufacturer_Part_Number=RC0603FR-0720KL, Package=0603
R22 R26 R72 R134: library part MCD-00070, "Resistor,1K,0603,1%,1/10W", Manufacturer=YAGEO, Manufacturer_Part_Number=RC0603FR-071KL, Package=0603
R24 R25 R32 R37 R38 R39 R40 R45 R46 R48 R52 R56 R58 R59 R66 R82 R83 R87 R91 R93 R95 R96 R98 R99 R100 R101: library part MCD-00455, "Resistor,33R,0402,1%,1/16W", Manufacturer=YAGEO, Manufacturer_Part_Number=RC0402FR-0733RL, Package=0402
R27 R28 R29 R30 R31 R117 R125 R135: library part MCD-00063, "Resistor,47K,0402,1%,1/16W", Manufacturer=YAGEO, Manufacturer_Part_Number=RC0402FR-0747KL, Package=0402
R34: library part MCD-01118, "Resistor,56R,0805,1%", Manufacturer=YAGEO, Manufacturer_Part_Number=RC0805FR-0756RL, Package=0805
R35 R36: library part MCD-00485, "Resistor,51R,0402,1%,1/16W", Manufacturer=YAGEO, Manufacturer_Part_Number=RC0402FR-0751RL, Package=0402
R41 R49 R50 R51 R57 R63 R64 R65 R67 R70 R71 R81 R94 R102 R105 R115 R120 R122 R124 R127 R129 R149 R154: library part MCD-00053, "Resistor,10K,0402,1%,1/16W", Manufacturer=YAGEO, Manufacturer_Part_Number=RC0402FR-0710KL, Package=0402
R43: library part MCD-01119, "Resistor,0.47R,1206,1%", Manufacturer=YAGEO, Manufacturer_Part_Number=RL1206FR-070R47L, Package=1206
R47 R144 R145: library part MCD-00225, "Resistor,510R,0603,1%,1/10W", Manufacturer=YAGEO, Manufacturer_Part_Number=RC0603FR-07510RL, Package=0603
R53 R60: library part MCD-00194, "Resistor, 120R, 0402, +/-1%, 1/16W", Manufacturer=YAGEO, Manufacturer_Part_Number=RC0402FR-07120RL, Package=0402
R54 R62: library part MCD-00181, "Resistor,0R,0603,ULO", Manufacturer="ROHM SEMICONDUCTOR", Manufacturer_Part_Number=PMR03EZPJ000, Package=0603
R55 R90 R92: library part MCD-00068, "Resistor,1K5,0402,1%,1/16W", Manufacturer=YAGEO, Manufacturer_Part_Number=RC0402FR-071K5L, Package=0402
R68 R88 R97 R111 R140 R146: library part MCD-00067, "Resistor, 100R, 0402, +/- 1%, 1/16W", Manufacturer=YAGEO, Manufacturer_Part_Number=RC0402FR-07100RL, Package=0402
R69: library part MCD-01116, "Resistor,124K,0603,1%", Manufacturer=YAGEO, Manufacturer_Part_Number=RC0603FR-07124KL, Package=0603
R73: library part MCD-00257, "Resistor,1M,0603,1%,1/10W", Manufacturer=YAGEO, Manufacturer_Part_Number=RC0603FR-071ML, Package=0603
R74: library part MCD-01117, "Resistor,2K,0805,1%", Manufacturer=YAGEO, Manufacturer_Part_Number=RC0805FR-072KL, Package=0805
R75: library part MCD-00522, "Resistor,75K,0603,1%,1/10W", Manufacturer=YAGEO, Manufacturer_Part_Number=RC0603FR-0775KL, Package=0603
R76 R77 R78 R79: library part MCD-00565, "Resistor,49R9,0402,1%,1/16W", Manufacturer=YAGEO, Manufacturer_Part_Number=RC0402FR-0749R9L, Package=0402
R80: library part MCD-00723, "Resistor,12K1,0402,1%,1/16W", Manufacturer=YAGEO, Manufacturer_Part_Number=RC0402FR-0712K1L, Package=0402
R84 R85: library part MCD-00345, "Resistor,20R,0603,1%,1/10W", Manufacturer=YAGEO, Manufacturer_Part_Number=RC0603FR-0720RL, Package=0603
R86: library part MCD-00219, "Resistor,4K7,0603,1%,1/10W", Manufacturer=YAGEO, Manufacturer_Part_Number=RC0603FR-074K7L, Package=0603
R89: library part MCD-00185, "Resistor,3K,0402,1%,1/16W", Manufacturer=YAGEO, Manufacturer_Part_Number=RC0402FR-073KL, Package=0402
R103 R104 R106 R108 R110 R114 R147 R148 R150 R151 R152 R153: library part MCD-00189, "Resistor,22R,0402,1%,1/16W", Manufacturer=YAGEO, Manufacturer_Part_Number=RC0402FR-0722RL, Package=0402
R107: library part MCD-00055, "Resistor,2K7,0402,1%,1/16W", Manufacturer=YAGEO, Manufacturer_Part_Number=RC0402FR-072K7L, Package=0402
R109 R112 R113: library part MCD-00065, "Resistor,4K7,0402,1%,1/16W", Alternate_Manufacturer=YAGEO, Alternate_Manufacturer_Part_Number=RT0402FRE074K7L, Manufacturer_Part_Number=RC0402FR-074K7L, Package=0402
R116 R128 R136: library part MCD-00052, "Resistor,0R,0402,5%,1/16W", Manufacturer=YAGEO, Manufacturer_Part_Number=RC0402JR-070RL, Package=0402
R118: library part MCD-00499, "Resistor,620R,0402,1%,1/16W", Manufacturer=YAGEO, Manufacturer_Part_Number=RC0402FR-07620RL, Package=0402
R119 R121 R123: library part MCD-00194, "Resistor,120R,0402,1%,1/16W", Manufacturer=YAGEO, Manufacturer_Part_Number=RC0402FR-07120RL, Package=0402
R126: library part MCD-00061, "Resistor,1K,0402,1%,1/16W", Manufacturer=YAGEO, Manufacturer_Part_Number=RC0402FR-071KL, Package=0402
R130 R131: library part MCD-00197, "Resistor,330R,0603,1%,1/10W", Manufacturer=YAGEO, Manufacturer_Part_Number=RC0603FR-07330RL, Package=0603
R133: library part MCD-00429, "Resistor,22K,0402,1%,1/16W", Manufacturer=YAGEO, Manufacturer_Part_Number=RC0402FR-0722KL, Package=0402
R142: library part MCD-00164, "Resistor,220K,0402,1%,1/16W", Manufacturer=YAGEO, Manufacturer_Part_Number=RC0402FR-07220KL, Package=0402
R143: library part MCD-00508, "Resistor,680R,0603,1%,1/10W", Manufacturer=YAGEO, Manufacturer_Part_Number=RC0603FR-07680RL, Package=0603
SB1 SB2 SB3 SB4 SB5 SB6 SB7 SB8 SB9 SB10 SB11 SB12 SB13 SB14 SB15 SB16 SB17 SB18 SB19 SB20 SB21 SB22 SB23 SB24 SB25 SB26 SB27 SB28 SB29 SB30 SB31 SB32 SB33 SB34 SB35 SB36 SB37 SB38 SB39 SB40 SB41 SB42 SB43 SB44: library part MCD-00071, "Solder Bridge ON", Manufacturer=YAGEO, Manufacturer_Part_Number=RC0603JR-070RL, Package=SB0603
SW1: library part MCD-00566, "Mechanical Slide Switches 1K2 BLK ACT GOLD STRT MNT", Manufacturer=EAO, Manufacturer_Part_Number=09.03290.01
T1: library part MCD-01063, "Flyback Transformers for 3 Watt, PoE applications", Manufacturer="WURTH ELEKTRONIK", Manufacturer_Part_Number=750315923
T2: library part MCD-01081, "Flyback Transformers for 3 Watt, PoE applications, CoilCraft Cyntec", Manufacturer=COILCRAFT
T3: library part MCD-01067, "10/100BASE-TX VoIP Magnetics Modules, Data Transformer", Manufacturer="PULSE ELECTRONICS"
T4: library part MCD-01086, "Annel 200 V, 1.1ohm, 1 A, low gate charge STripFET II, Power MOSFET", Manufacturer=STMICROELECTRONICS, Manufacturer_HQ_COO=EU, Package=SOT-223
T5: library part MCD-01969, "Transistor, N-channel enhancement mode field-effect transistor", Manufacturer=NEXPERIA, Manufacturer_Part_Number=BSN20BK
TP1 TP2 TP4 TP5: library part MCD-00630, "Test Point 0.3mm", Manufacturer=N/A
TP3: library part MCD-00074, "Test Point 1mm", Manufacturer=n/a
U1: library part MCD-01138, "IC VREF SERIES 2.5V 8VSSOP", Manufacturer="TEXAS INSTRUMENTS", Package=VSSOP8
U2: library part MCD-03054, "IC, Half-Pitch Phototransistor Optocoupler, DC Input, 3750V, 4-pin SO", Manufacturer="BROADCOM LIMITED", Manufacturer_Part_Number=ACPL-217-560E, Package="4-pin SO"
U3: library part MCD-01089, "Low voltage adjustable shunt reference", Manufacturer=STMICROELECTRONICS, Manufacturer_HQ_COO=EU, Package=SOT23-5
U4 U5: library part MCD-00667, "4-line ESD protection for high speed lines", Manufacturer=STMICROELECTRONICS, Manufacturer_HQ_COO=EU, Package=uQFN-10L
U6: library part MCD-01673, "STM32H725IGK6 MCU, Cut1.0, 10x10x0.6mm, Pitch0.65mm, Int SMPS", Manufacturer=STMICROELECTRONICS, Manufacturer_HQ_COO=EU, Manufacturer_Part_Number=STM32H725IGK6, Package=UFBGA176+25
U7: library part MCD-02091, "Memory, HyperRAM,128Mb,100MHz,3V,BGA24", Manufacturer=ISSI, Manufacturer_Part_Number=IS66WVH16M8DBLL-100B1LI, Package=FBGA24
U8: library part MCD-01080, "Integrated IEEE 802.3af compliant PoE-PD interface, and PWM controller with support of external source", Manufacturer=STMICROELECTRONICS, Manufacturer_HQ_COO=EU, Package=HTSSOP16
U9: library part MCD-00719, "10/100M RMII Ethernet transceiver", Manufacturer=MICROCHIP
U10: library part MCD-00246, "Memory,Octo-SPI-NOR,512Mb,2048x16,133MHz,3V,DTR,BGA24, CMOS MXSMIO", Manufacturer=MACRONIX, Package=BGA24
U11: library part MCD-00086, "Ultra low drop-low noise BiCMOS voltage, regulators low ESR capacitors compatible", Manufacturer=STMICROELECTRONICS, Manufacturer_HQ_COO=EU
U12: library part MCD-00079, "Multi-Channel Audio Hub CODEC for Smartphones", Manufacturer="CIRRUS LOGIC"
U13: library part MCD-00596, "STM32F723IEK  (STM32F7) BGA176", Manufacturer=STMICROELECTRONICS, Manufacturer_HQ_COO=EU, Manufacturer_Part_Number=STM32F723IEK6
U14: library part MCD-00078, "Ultra low drop-low noise BiCMOS voltage, regulators low ESR capacitors compatible", Manufacturer=STMICROELECTRONICS, Manufacturer_HQ_COO=EU
U15: library part MCD-00088, "IC REG LDO 5V 0.8A SOT223", Manufacturer=STMICROELECTRONICS, Manufacturer_HQ_COO=EU, Package=SOT-223
U16 U18: library part MCD-00136, "Dual Transil array for ESD protection", Manufacturer=STMICROELECTRONICS, Manufacturer_HQ_COO=EU
U17: library part MCD-01127, "IC REG LDO 3.3V 1.3A 6DFN", Manufacturer=STMICROELECTRONICS, Manufacturer_HQ_COO=EU, Package=DFN6
U19: library part MCD-00247, "Quad Bidir ESD protection", Manufacturer=STMICROELECTRONICS, Manufacturer_HQ_COO=EU
U20 U21 U22: library part MCD-00129, "High-Speed CAN Flexible Data Rate Transceiver", Manufacturer=MICROCHIP, Manufacturer_Part_Number=MCP2562FDT-H/SN
U23 U24: library part MCD-00159, "500mA, Enhanced single channel power switches with active high enable pin", Alternate_Manufacturer="TEXAS INSTRUMENTS", Alternate_Manufacturer_Part_Number=TPS2051C, Manufacturer=STMICROELECTRONICS, Manufacturer_HQ_COO=EU
U25: library part MCD-00250, "Very low capacitance ESD protection , 4 lines", Manufacturer=STMICROELECTRONICS, Manufacturer_HQ_COO=EU
U26 U27 U28: library part MCD-01358, "Automotive dual-line Transil, transient voltage suppressor (TVS) for CAN bus 36V. Compliant with interfaces in automotive: CAN-FD, LIN, FlexRay, MOST, SENT, USB", Manufacturer=STMICROELECTRONICS, Manufacturer_HQ_COO=EU, Manufacturer_Part_Number=ESDCAN05-2BWY, Package=SOT323-3L
U29: library part MCD-00649, "Common mode filter with ESD protection for USB 2.0 interface", Manufacturer=STMICROELECTRONICS, Manufacturer_HQ_COO=EU
U30 U31 U32: library part MCD-00251, "High power transient voltage suppressor, 7V breakdown", Manufacturer=STMICROELECTRONICS, Manufacturer_HQ_COO=EU, Manufacturer_Part_Number=ESDA7P60-1U1M
U33: library part MCD-01715, "MEMS audio sensor omnidirectional digital microphone for industrial applications", Manufacturer=STMICROELECTRONICS, Manufacturer_HQ_COO=EU, Manufacturer_Part_Number=IMP34DT05TR, Package=HCLGA-4LD
U34: library part MCD-00170, "ESD protection 6V1", Manufacturer=STMICROELECTRONICS, Manufacturer_HQ_COO=EU, Manufacturer_Part_Number=ESDALC6V1-1U2
X1 X3: library part MCD-00597, "Oscillator 25Mhz, +-50ppm, Vcc:3.3V typ, square wave: [0.1Vcc;0.9Vcc], Enable pin, SMD", Alternate_Manufacturer=NDK, Alternate_Manufacturer_Part_Number="NZ2520SB 25MHz END4869B", Manufacturer_Part_Number=NZ2520SH-25MHZ-END4869C, Package=2.5x2mm
X2: library part MCD-00091, "Crystal 32.768kHz, 6pF, +-20ppm, 50Kohms max, SMD", Manufacturer=NDK, Manufacturer_Part_Number=NX3215SA-32.768KHZ-EXS00A-MU00525, Package=3.2x1.5mm

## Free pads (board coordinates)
  round 0.508 on Mech16: 1(47.923,-29.756) 1(96.771,-29.756)

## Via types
v1: diameter 0.45, hole 0.2, Top Layer to Bottom Layer, tented both sides, 1099 vias
v2: diameter 0.25, hole 0.1, Top Layer to Signal Layer 1, tented both sides, 217 vias
v3: diameter 0.25, hole 0.1, Signal Layer 4 to Bottom Layer, tented both sides, 53 vias
v4: diameter 0.6, hole 0.3, Top Layer to Bottom Layer, tented both sides, 9 vias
